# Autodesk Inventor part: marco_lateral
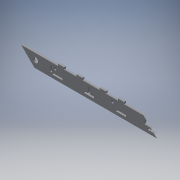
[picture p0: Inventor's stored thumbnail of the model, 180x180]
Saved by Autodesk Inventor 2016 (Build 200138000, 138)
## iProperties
Created: 2017-06
Part Number: marco_lateral
Material: Generic
Document SubType Name: Modeling
Designer: laboratorioesan
Density: 1 g/cm^3
Appearance: Default
Author: laboratorioesan
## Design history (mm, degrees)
sketch "Sketch1"
  geometry: L1 (0, 0)-(-1550, 0); L2 (-1550, -130)-(0, -130); L3 (-1550, -102.5)-(-1568, -102.5); L4 (-1568, -102.5)-(-1568, -27.5); L5 (-1568, -27.5)-(-1550, -27.5); L6 (-1550, 0)-(-1550, -27.5); L7 (-1550, -102.5)-(-1550, -130); L8 (0, -102.5)-(18, -102.5); L9 (18, -102.5)-(18, -27.5); L10 (18, -27.5)-(0, -27.5); L11 (0, -130)-(0, -102.5); L12 (0, -27.5)-(0, 0); 4 further points
  constraints: 24 end point, 6 perpendicular, 4 horizontal, 2 horizontal alignment, 2 midpoint, 2 parallel
  dimensions: "d0" = 1550 distance of L1.start L1.end; "d1" = 130 distance of L1.end L2.start; "d2" = 75 distance of L4.end L3.end; "d3" = 75 distance of L9.end L8.end; "d6" = 18 distance of L5.end L4.end; "d7" = 18 distance of L10.end L9.end
extrude "Extrusion1" new body sketch "Sketch1" distance "d4" = 18.5; taper "d5" = 0 deg
sketch "Sketch2"
  geometry: L1 (0, 0)-(1550, 0) reference; L2 (1550, 0)-(1550, 27.5) reference; L3 (1550, 27.5)-(1568, 27.5) reference; L4 (1568, 27.5)-(1568, 102.5) reference; L5 (1568, 102.5)-(1550, 102.5) reference; L6 (1550, 102.5)-(1550, 130) reference; L7 (1550, 130)-(0, 130) reference; L8 (0, 130)-(0, 102.5) reference; L9 (0, 102.5)-(-18, 102.5) reference; L10 (-18, 102.5)-(-18, 27.5) reference; L11 (-18, 27.5)-(0, 27.5) reference; L12 (0, 27.5)-(0, 0) reference; L13 (-18, 102.5)-(-18, 27.5) reference; C1 r 22.5 at (250, 65); C2 r 22.5 at (1350, 65); 4 further points
  constraints: 3 midpoint, 2 centre point, 2 horizontal alignment, 1 equal radius
  dimensions: "d9" = 45 diameter of C1; "d10" = 250 horizontal distance of point (0, 0) C1.centre; "d11" = 200 horizontal distance of L2.end C2.centre
extrude "Extrusion3" cut sketch "Sketch2" distance "d14" = 18.5; taper "d15" = 0 deg
sketch "Sketch3"
  geometry: L1 (0, 0)-(1550, 0) reference; L2 (1550, 0)-(1550, 27.5) reference; L3 (1550, 27.5)-(1568, 27.5) reference; L4 (1568, 27.5)-(1568, 102.5) reference; L5 (1568, 102.5)-(1550, 102.5) reference; L6 (1550, 102.5)-(1550, 130) reference; L7 (1550, 130)-(0, 130) reference; L8 (0, 130)-(0, 102.5) reference; L9 (0, 102.5)-(-18, 102.5) reference; L10 (-18, 102.5)-(-18, 27.5) reference; L11 (-18, 27.5)-(0, 27.5) reference; L12 (0, 27.5)-(0, 0) reference; L13 (1350, 84.5)-(1450, 84.5); L14 (1450, 84.5)-(1450, 100); L15 (1450, 100)-(1350, 100); L16 (1350, 100)-(1350, 84.5); L17 (1137.5, 100)-(1037.5, 100); L18 (1037.5, 100)-(1037.5, 84.5); L19 (1037.5, 84.5)-(1137.5, 84.5); L20 (1137.5, 84.5)-(1137.5, 100); L21 (825, 100)-(725, 100); L22 (725, 100)-(725, 84.5); L23 (725, 84.5)-(825, 84.5); L24 (825, 84.5)-(825, 100); L25 (512.5, 100)-(412.5, 100); L26 (412.5, 100)-(412.5, 84.5); L27 (412.5, 84.5)-(512.5, 84.5); L28 (512.5, 84.5)-(512.5, 100); L29 (200, 84.5)-(100, 84.5); L30 (100, 84.5)-(100, 100); L31 (100, 100)-(200, 100); L32 (200, 100)-(200, 84.5); C1 r 22.5 at (250, 65) reference; 1 further point
  constraints: 40 end point, 10 parallel, 6 point on line, 5 horizontal, 5 perpendicular, 4 collinear, 2 horizontal alignment
  dimensions: "d20" = 15.5 distance of L15.end L13.start; "d21" = 212.5 distance of L15.end L17.start; "d22" = 212.5 distance of L21.start L17.end; "d23" = 212.5 distance of L25.start L21.end; "d25" = 100 distance of L13.start L13.end; "d26" = 100 horizontal distance of L6.end L14.end; "d27" = 100 horizontal distance of L7.end L30.end; "d28" = 30 vertical distance of L14.end L6.end
extrude "Extrusion5" cut sketch "Sketch3" distance "d29" = 18.5; taper "d30" = 0 deg
sketch "Sketch4"
  geometry: L1 (200, 84.5)-(412.5, 84.5) reference; L2 (512.5, 84.5)-(725, 84.5) reference; L3 (0, 0)-(1550, 0) reference; L4 (412.5, 24.5)-(394, 24.5); L5 (394, 24.5)-(394, 84.5); L6 (394, 84.5)-(412.5, 84.5); L7 (412.5, 84.5)-(412.5, 24.5); L8 (412.5, 84.5)-(412.5, 100) reference; L9 (412.5, 100)-(512.5, 100) reference; L10 (512.5, 100)-(512.5, 84.5) reference; L11 (512.5, 84.5)-(412.5, 84.5) reference; L12 (1037.5, 84.5)-(1037.5, 100) reference; L13 (1037.5, 100)-(1137.5, 100) reference; L14 (1137.5, 100)-(1137.5, 84.5) reference; L15 (1137.5, 84.5)-(1037.5, 84.5) reference; L16 (1450, 100)-(1450, 84.5) reference; L17 (1450, 84.5)-(1350, 84.5) reference; L18 (1350, 84.5)-(1350, 100) reference; L19 (1350, 100)-(1450, 100) reference; L20 (725, 84.5)-(725, 100) reference; L21 (725, 100)-(825, 100) reference; L22 (825, 100)-(825, 84.5) reference; L23 (825, 84.5)-(725, 84.5) reference; L24 (200, 100)-(200, 84.5) reference; L25 (200, 84.5)-(100, 84.5) reference; L26 (100, 84.5)-(100, 100) reference; L27 (100, 100)-(200, 100) reference; L28 (0, 0)-(1550, 0) reference; L29 (1550, 0)-(1550, 27.5) reference; L30 (1550, 27.5)-(1568, 27.5) reference; L31 (1568, 27.5)-(1568, 102.5) reference; L32 (1568, 102.5)-(1550, 102.5) reference; L33 (1550, 102.5)-(1550, 130) reference; L34 (1550, 130)-(0, 130) reference; L35 (0, 130)-(0, 102.5) reference; L36 (0, 102.5)-(-18, 102.5) reference; L37 (-18, 102.5)-(-18, 27.5) reference; L38 (-18, 27.5)-(0, 27.5) reference; L39 (0, 27.5)-(0, 0) reference; L40 (781, 24.5)-(762.5, 24.5); L41 (762.5, 24.5)-(762.5, 84.5); L42 (762.5, 84.5)-(781, 84.5); L43 (781, 84.5)-(781, 24.5); C1 r 22.5 at (250, 65) reference
  constraints: 16 end point, 4 parallel, 2 horizontal, 2 horizontal alignment, 2 perpendicular, 1 point on line
  dimensions: "d31" = 18.5 distance of L4.start L4.end; "d32" = 60 distance of L6.end L4.start; "d33" = 0 distance of L6.end L1.end; "d34" = 18.5 distance of L41.end L42.end; "d35" = 350 distance of L4.start L40.end
extrude "Extrusion6" cut sketch "Sketch4" distance "d36" = 18.5; taper "d37" = 0 deg
sketch "Sketch5"
  geometry: L1 (0, 0)-(1550, 0) reference; L2 (1550, 0)-(1550, 27.5) reference; L3 (1550, 27.5)-(1568, 27.5) reference; L4 (1568, 27.5)-(1568, 102.5) reference; L5 (1568, 102.5)-(1550, 102.5) reference; L6 (1550, 102.5)-(1550, 130) reference; L7 (1550, 130)-(0, 130) reference; L8 (0, 130)-(0, 102.5) reference; L9 (0, 102.5)-(-18, 102.5) reference; L10 (-18, 102.5)-(-18, 27.5) reference; L11 (-18, 27.5)-(0, 27.5) reference; L12 (0, 27.5)-(0, 0) reference; L13 (200, 100)-(200, 84.5) reference; L14 (200, 84.5)-(100, 84.5) reference; L15 (100, 84.5)-(100, 100) reference; L16 (100, 100)-(200, 100) reference; L17 (1450, 100)-(1450, 84.5) reference; L18 (1450, 84.5)-(1350, 84.5) reference; L19 (1350, 84.5)-(1350, 100) reference; L20 (1350, 100)-(1450, 100) reference; L21 (1037.5, 84.5)-(1037.5, 100) reference; L22 (1037.5, 100)-(1137.5, 100) reference; L23 (1137.5, 100)-(1137.5, 84.5) reference; L24 (1137.5, 84.5)-(1037.5, 84.5) reference; L25 (412.5, 84.5)-(412.5, 100) reference; L26 (412.5, 100)-(512.5, 100) reference; L27 (512.5, 100)-(512.5, 84.5) reference; L28 (512.5, 84.5)-(412.5, 84.5) reference; L29 (412.5, 84.5)-(412.5, 24.5) reference; L30 (412.5, 24.5)-(394, 24.5) reference; L31 (394, 24.5)-(394, 84.5) reference; L32 (394, 84.5)-(412.5, 84.5) reference; L33 (762.5, 24.5)-(762.5, 84.5) reference; L34 (762.5, 84.5)-(725, 84.5) reference; L35 (725, 84.5)-(725, 100) reference; L36 (725, 100)-(825, 100) reference; L37 (825, 100)-(825, 84.5) reference; L38 (825, 84.5)-(781, 84.5) reference; L39 (781, 84.5)-(781, 24.5) reference; L40 (781, 24.5)-(762.5, 24.5) reference; L41 (0, 0)-(1550, 0) reference; L42 (709.863, 0)-(649.863, 0); L43 (649.863, 0)-(649.863, -18); L44 (649.863, -18)-(709.863, -18); L45 (709.863, -18)-(709.863, 0); L46 (529.863, 0)-(469.863, 0); L47 (469.863, 0)-(469.863, -18); L48 (469.863, -18)-(529.863, -18); L49 (529.863, -18)-(529.863, 0); L50 (937.5, 0)-(877.5, 0); L51 (877.5, 0)-(877.5, -18); L52 (877.5, -18)-(937.5, -18); L53 (937.5, -18)-(937.5, 0); L54 (1117.5, 0)-(1057.5, 0); L55 (1057.5, 0)-(1057.5, -18); L56 (1057.5, -18)-(1117.5, -18); L57 (1117.5, -18)-(1117.5, 0); C1 r 22.5 at (250, 65) reference; 2 further points
  constraints: 32 end point, 8 parallel, 5 point on line, 4 horizontal, 4 perpendicular, 2 midpoint, 1 vertical alignment
  dimensions: "d38" = 60 distance of L44.end L43.end; "d39" = 18 distance of L43.end L42.end; "d40" = 60 distance of L48.end L47.end; "d42" = 60 distance of L52.end L51.end; "d43" = 60 distance of L56.end L55.end; "d44" = 120 distance of L50.start L54.end; "d45" = 120 distance of L46.start L42.end
extrude "Extrusion7" join sketch "Sketch5" distance "d46" = 18.5; taper "d47" = 0 deg
sketch "Sketch6"
  geometry: L1 (762.5, -18.5)-(781, -18.5) reference; L2 (993.977, 0)-(993.977, -18.5) reference; L3 (1012.477, 0)-(1012.477, -18.5) reference; L4 (432.59, 0)-(432.59, -18.5) reference; L5 (451.09, 0)-(451.09, -18.5) reference; L6 (0, 0)-(469.863, 0) reference; L7 (469.863, 0)-(469.863, -18) reference; L8 (469.863, -18)-(529.863, -18) reference; L9 (529.863, -18)-(529.863, 0) reference; L10 (529.863, 0)-(649.863, 0) reference; L11 (649.863, 0)-(649.863, -18) reference; L12 (649.863, -18)-(709.863, -18) reference; L13 (709.863, -18)-(709.863, 0) reference; L14 (709.863, 0)-(877.5, 0) reference; L15 (877.5, 0)-(877.5, -18) reference; L16 (877.5, -18)-(937.5, -18) reference; L17 (937.5, -18)-(937.5, 0) reference; L18 (937.5, 0)-(1057.5, 0) reference; L19 (1057.5, 0)-(1057.5, -18) reference; L20 (1057.5, -18)-(1117.5, -18) reference; L21 (1117.5, -18)-(1117.5, 0) reference; L22 (1117.5, 0)-(1550, 0) reference; L23 (1550, 0)-(1550, 27.5) reference; L24 (1550, 27.5)-(1568, 27.5) reference; L25 (1568, 27.5)-(1568, 102.5) reference; L26 (1568, 102.5)-(1550, 102.5) reference; L27 (1550, 102.5)-(1550, 130) reference; L28 (1550, 130)-(0, 130) reference; L29 (0, 130)-(0, 102.5) reference; L30 (0, 102.5)-(-18, 102.5) reference; L31 (-18, 102.5)-(-18, 27.5) reference; L32 (-18, 27.5)-(0, 27.5) reference; L33 (0, 27.5)-(0, 0) reference; L34 (200, 100)-(200, 84.5) reference; L35 (200, 84.5)-(100, 84.5) reference; L36 (100, 84.5)-(100, 100) reference; L37 (100, 100)-(200, 100) reference; L38 (1450, 100)-(1450, 84.5) reference; L39 (1450, 84.5)-(1350, 84.5) reference; L40 (1350, 84.5)-(1350, 100) reference; L41 (1350, 100)-(1450, 100) reference; L42 (1037.5, 84.5)-(1037.5, 100) reference; L43 (1037.5, 100)-(1137.5, 100) reference; L44 (1137.5, 100)-(1137.5, 84.5) reference; L45 (1137.5, 84.5)-(1037.5, 84.5) reference; L46 (412.5, 84.5)-(412.5, 100) reference; L47 (412.5, 100)-(512.5, 100) reference; L48 (512.5, 100)-(512.5, 84.5) reference; L49 (512.5, 84.5)-(412.5, 84.5) reference; L50 (412.5, 84.5)-(412.5, 24.5) reference; L51 (412.5, 24.5)-(394, 24.5) reference; L52 (394, 24.5)-(394, 84.5) reference; L53 (394, 84.5)-(412.5, 84.5) reference; L54 (762.5, 24.5)-(762.5, 84.5) reference; L55 (762.5, 84.5)-(725, 84.5) reference; L56 (725, 84.5)-(725, 100) reference; L57 (725, 100)-(825, 100) reference; L58 (825, 100)-(825, 84.5) reference; L59 (825, 84.5)-(781, 84.5) reference; L60 (781, 84.5)-(781, 24.5) reference; L61 (781, 24.5)-(762.5, 24.5) reference; L62 (1012.477, 20)-(993.977, 20); L63 (993.977, 20)-(993.977, 50); L64 (993.977, 50)-(1012.477, 50)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; C1 r 22.5 at (250, 65) reference; 1 further point
  constraints: 26 end point, 4 parallel, 4 vertical, 3 horizontal, 2 perpendicular, 10 other
  dimensions: "d48" = 30 distance of L62.end L63.end; "d49" = 20 distance of L3.start L62.start
extrude "Extrusion8" cut sketch "Sketch6" distance "d50" = 18.5; taper "d51" = 0 deg
sketch "Sketch7"
  geometry: L1 (1012.477, -20)-(1012.477, -50) reference; L2 (1012.477, -50)-(993.977, -50) reference; L3 (993.977, -50)-(993.977, -20) reference; L4 (993.977, -20)-(1012.477, -20) reference; L5 (451.09, -20)-(451.09, -50) reference; L6 (451.09, -50)-(432.59, -50) reference; L7 (432.59, -50)-(432.59, -20) reference; L8 (432.59, -20)-(451.09, -20) reference; L9 (412.5, -100)-(412.5, -84.5) reference; L10 (412.5, -84.5)-(394, -84.5) reference; L11 (394, -84.5)-(394, -24.5) reference; L12 (394, -24.5)-(412.5, -24.5) reference; L13 (412.5, -24.5)-(412.5, -84.5) reference; L14 (412.5, -84.5)-(512.5, -84.5) reference; L15 (512.5, -84.5)-(512.5, -100) reference; L16 (512.5, -100)-(412.5, -100) reference; L17 (1037.5, -100)-(1037.5, -84.5) reference; L18 (1037.5, -84.5)-(1137.5, -84.5) reference; L19 (1137.5, -84.5)-(1137.5, -100) reference; L20 (1137.5, -100)-(1037.5, -100) reference; L21 (1450, -84.5)-(1450, -100) reference; L22 (1450, -100)-(1350, -100) reference; L23 (1350, -100)-(1350, -84.5) reference; L24 (1350, -84.5)-(1450, -84.5) reference; L25 (762.5, -84.5)-(762.5, -24.5) reference; L26 (762.5, -24.5)-(781, -24.5) reference; L27 (781, -24.5)-(781, -84.5) reference; L28 (781, -84.5)-(825, -84.5) reference; L29 (825, -84.5)-(825, -100) reference; L30 (825, -100)-(725, -100) reference; L31 (725, -100)-(725, -84.5) reference; L32 (725, -84.5)-(762.5, -84.5) reference; L33 (200, -84.5)-(200, -100) reference; L34 (200, -100)-(100, -100) reference; L35 (100, -100)-(100, -84.5) reference; L36 (100, -84.5)-(200, -84.5) reference; L37 (0, 0)-(469.863, 0) reference; L38 (0, -27.5)-(0, 0) reference; L39 (-18, -27.5)-(0, -27.5) reference; L40 (-18, -102.5)-(-18, -27.5) reference; L41 (0, -102.5)-(-18, -102.5) reference; L42 (0, -130)-(0, -102.5) reference; L43 (1550, -130)-(0, -130) reference; L44 (1550, -102.5)-(1550, -130) reference; L45 (1568, -102.5)-(1550, -102.5) reference; L46 (1568, -27.5)-(1568, -102.5) reference; L47 (1550, -27.5)-(1568, -27.5) reference; L48 (1550, 0)-(1550, -27.5) reference; L49 (1117.5, 0)-(1550, 0) reference; L50 (1117.5, 0)-(1117.5, 18) reference; L51 (1117.5, 18)-(1057.5, 18) reference; L52 (1057.5, 18)-(1057.5, 0) reference; L53 (937.5, 0)-(1057.5, 0) reference; L54 (937.5, 0)-(937.5, 18) reference; L55 (937.5, 18)-(877.5, 18) reference; L56 (877.5, 18)-(877.5, 0) reference; L57 (709.863, 0)-(877.5, 0) reference; L58 (709.863, 0)-(709.863, 18) reference; L59 (709.863, 18)-(649.863, 18) reference; L60 (649.863, 18)-(649.863, 0) reference; L61 (529.863, 0)-(649.863, 0) reference; L62 (529.863, 0)-(529.863, 18) reference; L63 (529.863, 18)-(469.863, 18) reference; L64 (469.863, 18)-(469.863, 0) reference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; C1 r 22.5 at (250, -65) reference; 1 further point
  constraints: 8 end point, 2 parallel, 1 horizontal, 1 perpendicular
  dimensions: "d52" = 15 distance between parallel lines of L66 L67; "d53" = 15 distance between parallel lines of L24 L69
extrude "Extrusion9" cut sketch "Sketch7" distance "d54" = 18.5; taper "d55" = 0 deg
sketch "Sketch8"
  geometry: L1 (1315.972, 35.5)-(1315.972, 69.5) reference; L2 (1315.972, 69.5)-(1518.516, 69.5) reference; L3 (1518.516, 69.5)-(1518.516, 35.5) reference; L4 (1518.516, 35.5)-(1315.972, 35.5) reference; L5 (1012.477, 50)-(1012.477, 20) reference; L6 (1012.477, 20)-(993.977, 20) reference; L7 (993.977, 20)-(993.977, 50) reference; L8 (993.977, 50)-(1012.477, 50) reference; L9 (451.09, 50)-(451.09, 20) reference; L10 (451.09, 20)-(432.59, 20) reference; L11 (432.59, 20)-(432.59, 50) reference; L12 (432.59, 50)-(451.09, 50) reference; L13 (0, 0)-(469.863, 0) reference; L14 (469.863, 0)-(469.863, -18) reference; L15 (469.863, -18)-(529.863, -18) reference; L16 (529.863, -18)-(529.863, 0) reference; L17 (529.863, 0)-(649.863, 0) reference; L18 (649.863, 0)-(649.863, -18) reference; L19 (649.863, -18)-(709.863, -18) reference; L20 (709.863, -18)-(709.863, 0) reference; L21 (709.863, 0)-(877.5, 0) reference; L22 (877.5, 0)-(877.5, -18) reference; L23 (877.5, -18)-(937.5, -18) reference; L24 (937.5, -18)-(937.5, 0) reference; L25 (937.5, 0)-(1057.5, 0) reference; L26 (1057.5, 0)-(1057.5, -18) reference; L27 (1057.5, -18)-(1117.5, -18) reference; L28 (1117.5, -18)-(1117.5, 0) reference; L29 (1117.5, 0)-(1550, 0) reference; L30 (1550, 0)-(1550, 27.5) reference; L31 (1550, 27.5)-(1568, 27.5) reference; L32 (1568, 27.5)-(1568, 102.5) reference; L33 (1568, 102.5)-(1550, 102.5) reference; L34 (1550, 102.5)-(1550, 130) reference; L35 (1550, 130)-(0, 130) reference; L36 (0, 130)-(0, 102.5) reference; L37 (0, 102.5)-(-18, 102.5) reference; L38 (-18, 102.5)-(-18, 27.5) reference; L39 (-18, 27.5)-(0, 27.5) reference; L40 (0, 27.5)-(0, 0) reference; L41 (200, 100)-(200, 84.5) reference; L42 (200, 84.5)-(100, 84.5) reference; L43 (100, 84.5)-(100, 100) reference; L44 (100, 100)-(200, 100) reference; L45 (1450, 100)-(1450, 84.5) reference; L46 (1450, 84.5)-(1350, 84.5) reference; L47 (1350, 84.5)-(1350, 100) reference; L48 (1350, 100)-(1450, 100) reference; L49 (1037.5, 84.5)-(1037.5, 100) reference; L50 (1037.5, 100)-(1137.5, 100) reference; L51 (1137.5, 100)-(1137.5, 84.5) reference; L52 (1137.5, 84.5)-(1037.5, 84.5) reference; L53 (412.5, 84.5)-(412.5, 100) reference; L54 (412.5, 100)-(512.5, 100) reference; L55 (512.5, 100)-(512.5, 84.5) reference; L56 (512.5, 84.5)-(412.5, 84.5) reference; L57 (412.5, 84.5)-(412.5, 24.5) reference; L58 (412.5, 24.5)-(394, 24.5) reference; L59 (394, 24.5)-(394, 84.5) reference; L60 (394, 84.5)-(412.5, 84.5) reference; L61 (762.5, 24.5)-(762.5, 84.5) reference; L62 (762.5, 84.5)-(725, 84.5) reference; L63 (725, 84.5)-(725, 100) reference; L64 (725, 100)-(825, 100) reference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; C1 r 22.5 at (250, 65) reference; C2 r 25 at (250, 65); C3 r 11.5 at (250, 65); 1 further point
  constraints: 2 centre point, 2 coincident, 2 end point, 1 horizontal, 2 other
  dimensions: "d56" = 50 diameter of C2; "d57" = 23 diameter of C3
extrude "Extrusion10" join sketch "Sketch8" distance "d58" = 18.5; taper "d59" = 0 deg
sketch "Sketch9"
  geometry: L1 (1315.972, 35.5)-(1315.972, 69.5) reference; L2 (1315.972, 69.5)-(1518.516, 69.5) reference; L3 (1518.516, 69.5)-(1518.516, 35.5) reference; L4 (1518.516, 35.5)-(1315.972, 35.5) reference; L5 (1012.477, 50)-(1012.477, 20) reference; L6 (1012.477, 20)-(993.977, 20) reference; L7 (993.977, 20)-(993.977, 50) reference; L8 (993.977, 50)-(1012.477, 50) reference; L9 (451.09, 50)-(451.09, 20) reference; L10 (451.09, 20)-(432.59, 20) reference; L11 (432.59, 20)-(432.59, 50) reference; L12 (432.59, 50)-(451.09, 50) reference; L13 (0, 0)-(469.863, 0) reference; L14 (469.863, 0)-(469.863, -18) reference; L15 (469.863, -18)-(529.863, -18) reference; L16 (529.863, -18)-(529.863, 0) reference; L17 (529.863, 0)-(649.863, 0) reference; L18 (649.863, 0)-(649.863, -18) reference; L19 (649.863, -18)-(709.863, -18) reference; L20 (709.863, -18)-(709.863, 0) reference; L21 (709.863, 0)-(877.5, 0) reference; L22 (877.5, 0)-(877.5, -18) reference; L23 (877.5, -18)-(937.5, -18) reference; L24 (937.5, -18)-(937.5, 0) reference; L25 (937.5, 0)-(1057.5, 0) reference; L26 (1057.5, 0)-(1057.5, -18) reference; L27 (1057.5, -18)-(1117.5, -18) reference; L28 (1117.5, -18)-(1117.5, 0) reference; L29 (1117.5, 0)-(1550, 0) reference; L30 (1550, 0)-(1550, 27.5) reference; L31 (1550, 27.5)-(1568, 27.5) reference; L32 (1568, 27.5)-(1568, 102.5) reference; L33 (1568, 102.5)-(1550, 102.5) reference; L34 (1550, 102.5)-(1550, 130) reference; L35 (1550, 130)-(0, 130) reference; L36 (0, 130)-(0, 102.5) reference; L37 (0, 102.5)-(-18, 102.5) reference; L38 (-18, 102.5)-(-18, 27.5) reference; L39 (-18, 27.5)-(0, 27.5) reference; L40 (0, 27.5)-(0, 0) reference; L41 (200, 100)-(200, 84.5) reference; L42 (200, 84.5)-(100, 84.5) reference; L43 (100, 84.5)-(100, 100) reference; L44 (100, 100)-(200, 100) reference; L45 (1450, 100)-(1450, 84.5) reference; L46 (1450, 84.5)-(1350, 84.5) reference; L47 (1350, 84.5)-(1350, 100) reference; L48 (1350, 100)-(1450, 100) reference; L49 (1037.5, 84.5)-(1037.5, 100) reference; L50 (1037.5, 100)-(1137.5, 100) reference; L51 (1137.5, 100)-(1137.5, 84.5) reference; L52 (1137.5, 84.5)-(1037.5, 84.5) reference; L53 (412.5, 84.5)-(412.5, 100) reference; L54 (412.5, 100)-(512.5, 100) reference; L55 (512.5, 100)-(512.5, 84.5) reference; L56 (512.5, 84.5)-(412.5, 84.5) reference; L57 (412.5, 84.5)-(412.5, 24.5) reference; L58 (412.5, 24.5)-(394, 24.5) reference; L59 (394, 24.5)-(394, 84.5) reference; L60 (394, 84.5)-(412.5, 84.5) reference; L61 (762.5, 24.5)-(762.5, 84.5) reference; L62 (762.5, 84.5)-(725, 84.5) reference; L63 (725, 84.5)-(725, 100) reference; L64 (725, 100)-(825, 100) reference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; C1 r 24.9 at (250, 59.6); 1 further point
  constraints: 2 end point, 1 centre point, 1 horizontal, 1 tangent
  dimensions: "d60" = 49.8 diameter of C1; "d61" = 50 horizontal distance of L41.end C1.centre
extrude "Extrusion11" cut sketch "Sketch9" distance "d62" = 18.5; taper "d63" = 0 deg
body "Solid1"
node "Projected Loop1"
node "Projected Loop2"
node "Reference1"
node "Reference2"
node "Projected Loop3"
node "Projected Loop4"
node "Projected Loop5"
node "Projected Loop6"
node "Reference3"
node "Reference4"
node "Reference5"
node "Projected Loop7"
node "Projected Loop8"
